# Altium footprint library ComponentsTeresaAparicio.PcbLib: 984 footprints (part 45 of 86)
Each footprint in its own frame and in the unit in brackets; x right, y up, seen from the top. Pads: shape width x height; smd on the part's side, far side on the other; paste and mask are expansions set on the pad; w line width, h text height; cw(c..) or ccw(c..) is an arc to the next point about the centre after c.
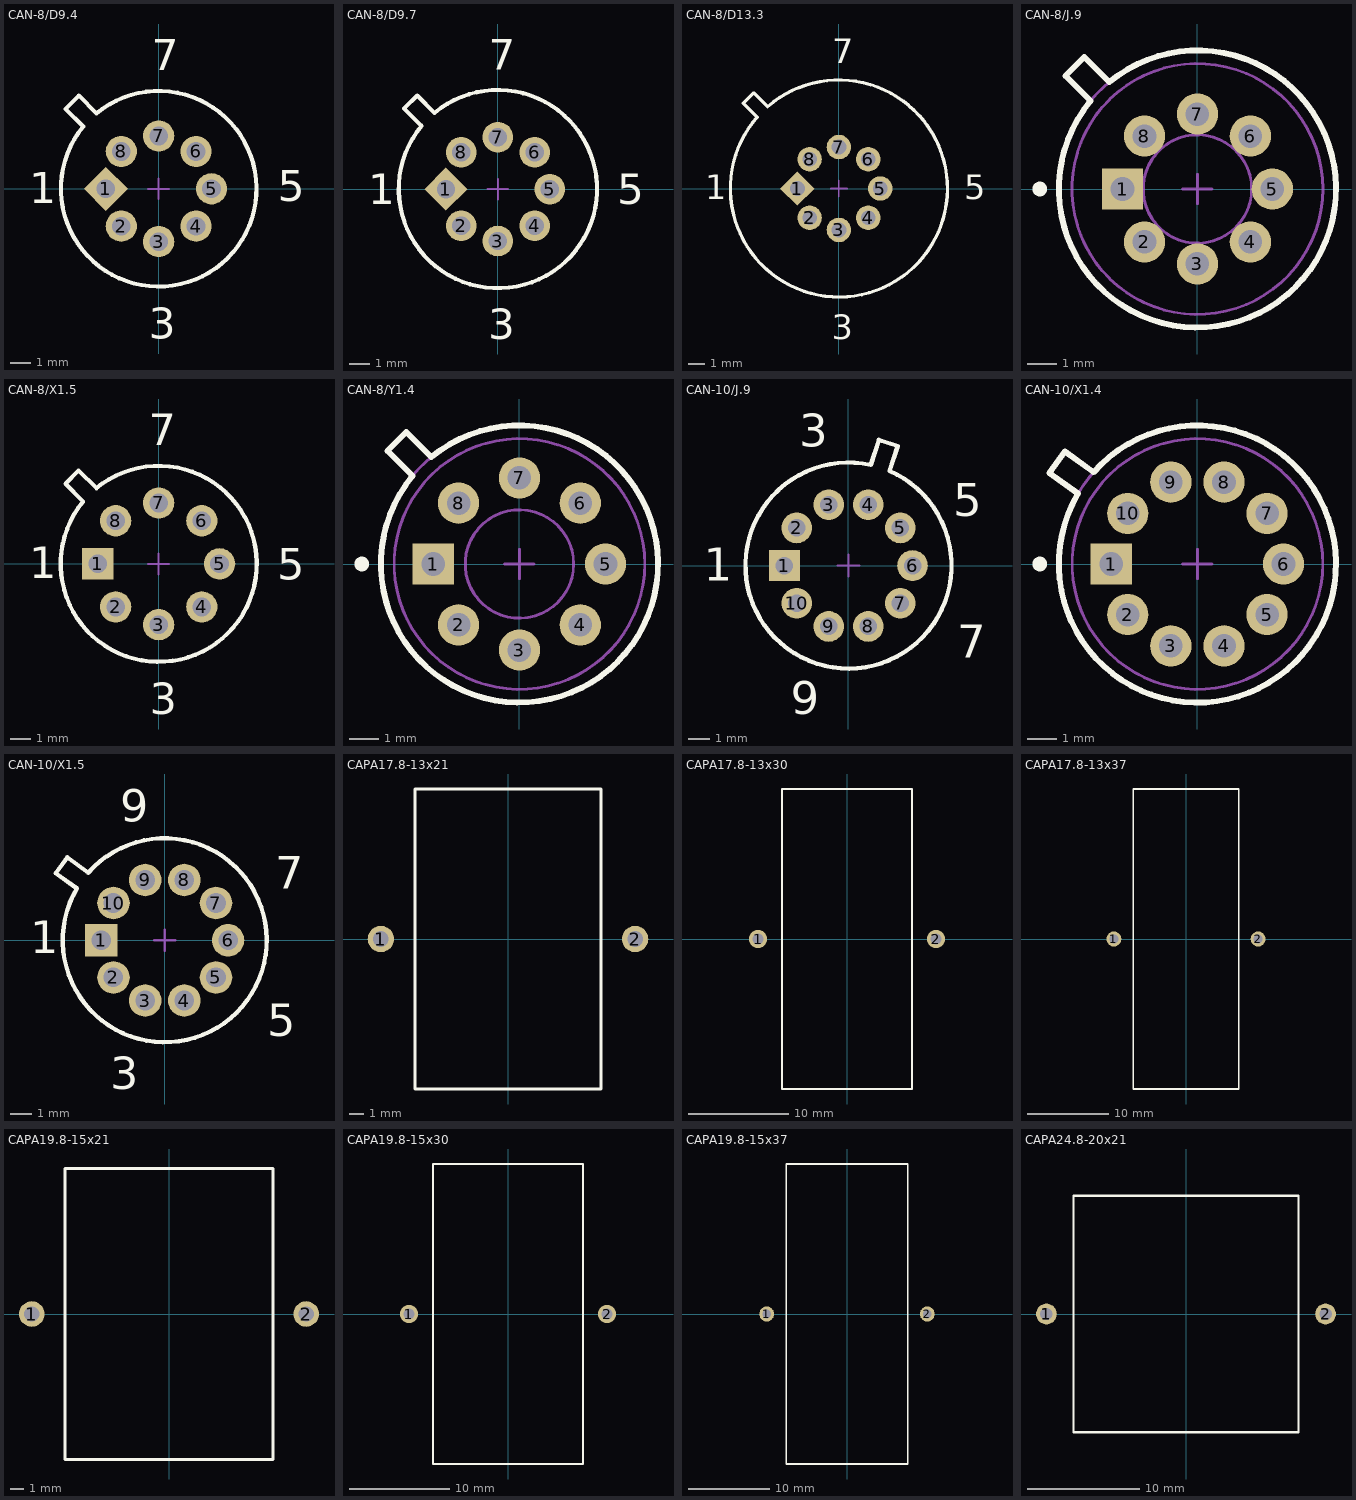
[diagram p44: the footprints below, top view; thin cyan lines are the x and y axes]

## CAN-8/D9.4 [mm] "Can; 8 Leads; Pin Circle Dia. 5.08 mm; Lead Dia. 0.53 mm (max)"
height 4.7
pads (8):
  rect 1.5x1.5 hole 0.9 rot 45: 1(-2.54,0)
  round 1.5 hole 0.9: 2(-1.796,-1.796) 3(0,-2.54) 4(1.796,-1.796) 5(2.54,0) 6(1.796,1.796) 7(0,2.54) 8(-1.796,1.796)
Top Overlay:
  lines w0.2: -4.475,3.838 -3.838,4.475 -2.99,3.626 cw(c0,0) -3.626,2.99 -4.475,3.838
  text "1" at -6.22,-0.696 h1.5
  text "3" at -0.469,-7.22 h1.5
  text "5" at 5.712,-0.589 h1.5
  text "7" at -0.332,5.7 h1.5
Mechanical 15:
  lines w0.1: -0.5,0 0.5,0 ; 0,-0.5 0,0.5

## CAN-8/D9.7 [mm] "Can; 8 Leads; Pin Circle Dia. 5.08 mm (TO-99); Lead Dia. 0.53 mm (max)"
height 5.72
pads (8):
  rect 1.5x1.5 hole 0.9 rot 45: 1(-2.54,0)
  round 1.5 hole 0.9: 2(-1.796,-1.796) 3(0,-2.54) 4(1.796,-1.796) 5(2.54,0) 6(1.796,1.796) 7(0,2.54) 8(-1.796,1.796)
Top Overlay:
  lines w0.2: -4.581,3.945 -3.733,3.096 ccw(c0,0) -3.096,3.733 -3.945,4.581 -4.581,3.945
  text "7" at -0.442,5.841 h1.5
  text "5" at 5.84,-0.737 h1.5
  text "3" at -0.479,-7.332 h1.5
  text "1" at -6.352,-0.737 h1.5
Mechanical 15:
  lines w0.1: -0.5,0 0.5,0 ; 0,-0.5 0,0.5

## CAN-8/D13.3 [mm] "Can; 8 Leads; Pin Circle Dia. 5.08 mm; Lead Dia. 0.53 mm (max)"
height 8.82
pads (8):
  rect 1.5x1.5 hole 0.9 rot 45: 1(-2.54,0)
  round 1.5 hole 0.9: 2(-1.796,-1.796) 3(0,-2.54) 4(1.796,-1.796) 5(2.54,0) 6(1.796,1.796) 7(0,2.54) 8(-1.796,1.796)
Top Overlay:
  lines w0.2: -5.858,5.222 -5.222,5.858 -4.373,5.01 cw(c0,0) -5.01,4.373 -5.858,5.222
  text "7" at -0.406,7.66 h1.5
  text "5" at 7.668,-0.667 h1.5
  text "3" at -0.431,-9.221 h1.5
  text "1" at -8.177,-0.667 h1.5
Mechanical 15:
  lines w0.1: -0.5,0 0.5,0 ; 0,-0.5 0,0.5

## CAN-8/J.9 [mm] "Can; 8 Leads; Pin Circle Dia. 5.08 mm; Lead Dia. 0.48 mm (max)"
height 5.56
pads (8):
  rect 1.4x1.4 hole 0.8: 1(-2.54,0)
  round 1.4 hole 0.8: 2(-1.796,-1.796) 3(0,-2.54) 4(1.796,-1.796) 5(2.54,0) 6(1.796,1.796) 7(0,2.54) 8(-1.796,1.796)
Top Overlay:
  circle w0.25: c-5.35,0 r0.125
  lines w0.2: -4.475,3.838 -3.626,2.99 ccw(c0,0) -2.99,3.626 -3.838,4.475 -4.475,3.838
Mechanical 13:
  circle w0.1: c0,0 r1.84
  circle w0.1: c0,0 r4.255
  circle w0.1: c0,0 r4.7
Mechanical 15:
  lines w0.1: -0.5,0 0.5,0 ; 0,-0.5 0,0.5
3D body: height 5.56, standoff 1.91, extent -4.264,-4.264 4.264,4.264
3D body: height 1.91, standoff 0.38, extent -4.71,-4.71 4.71,4.71
3D body: height 0.38, standoff 0, extent -1.848,-1.848 1.848,1.848

## CAN-8/X1.5 [mm] "Can; 8 Leads; Pin Circle Dia. 5.84 mm; Lead Dia. 0.53 mm (max)"
height 4.7
pads (8):
  rect 1.5x1.5 hole 0.9: 1(-2.92,0)
  round 1.5 hole 0.9: 2(-2.065,-2.065) 3(0,-2.92) 4(2.065,-2.065) 5(2.92,0) 6(2.065,2.065) 7(0,2.92) 8(-2.065,2.065)
Top Overlay:
  lines w0.2: -4.475,3.838 -3.626,2.99 ccw(c0,0) -2.99,3.626 -3.838,4.475 -4.475,3.838
  text "7" at -0.472,5.683 h1.5
  text "5" at 5.691,-0.769 h1.5
  text "3" at -0.436,-7.201 h1.5
  text "1" at -6.204,-0.697 h1.5
Mechanical 15:
  lines w0.1: -0.5,0 0.5,0 ; 0,-0.5 0,0.5

## CAN-8/Y1.4 [mm] "Can; 8 Leads; Pin Circle Dia. 5.84 mm; Lead Dia. 0.48 mm (max)"
height 5.08
pads (8):
  rect 1.4x1.4 hole 0.8: 1(-2.92,0)
  round 1.4 hole 0.8: 2(-2.065,-2.065) 3(0,-2.92) 4(2.065,-2.065) 5(2.92,0) 6(2.065,2.065) 7(0,2.92) 8(-2.065,2.065)
Top Overlay:
  circle w0.25: c-5.35,0 r0.125
  lines w0.2: -4.475,3.838 -3.626,2.99 ccw(c0,0) -2.99,3.626 -3.838,4.475 -4.475,3.838
Mechanical 13:
  circle w0.1: c0,0 r1.84
  circle w0.1: c0,0 r4.25
  circle w0.1: c0,0 r4.7
Mechanical 15:
  lines w0.1: -0.5,0 0.5,0 -0.5,0 ; 0,-0.5 0,0.5 0,-0.5
3D body: height 0.38, standoff 0, extent -1.848,-1.848 1.848,1.848
3D body: height 1.4, standoff 0.38, extent -4.71,-4.71 4.71,4.71
3D body: height 5.08, standoff 1.4, extent -4.259,-4.259 4.259,4.259

## CAN-10/J.9 [mm] "Can; 10 Leads; Pin Circle Dia. 5.84 mm; Lead Dia. 0.48 mm (max)"
height 4.7
pads (10):
  rect 1.4x1.4 hole 0.8: 1(-2.92,0)
  round 1.4 hole 0.8: 2(-2.362,1.716) 3(-0.902,2.777) 4(0.902,2.777) 5(2.362,1.716) 6(2.92,0) 7(2.362,-1.716) 8(0.902,-2.777) 9(-0.902,-2.777) 10(-2.362,-1.716)
Top Overlay:
  lines w0.2: 1.018,4.588 ccw(c0,0) 1.874,4.31 2.245,5.452 1.389,5.73 1.018,4.588
  text "1" at -6.596,-0.689 h1.5
  text "3" at -2.248,5.412 h1.5
  text "5" at 4.779,2.259 h1.5
  text "7" at 4.96,-4.21 h1.5
  text "9" at -2.636,-6.769 h1.5
Mechanical 15:
  lines w0.1: -0.5,0 0.5,0 ; 0,-0.5 0,0.5

## CAN-10/X1.4 [mm] "Can; 10 Leads; Pin Circle Dia. 5.84 mm; Lead Dia. 0.48 mm (max)"
height 4.7
pads (10):
  rect 1.4x1.4 hole 0.8: 1(-2.92,0)
  round 1.4 hole 0.8: 2(-2.362,-1.716) 3(-0.902,-2.777) 4(0.902,-2.777) 5(2.362,-1.716) 6(2.92,0) 7(2.362,1.716) 8(0.902,2.777) 9(-0.902,2.777) 10(-2.362,1.716)
Top Overlay:
  circle w0.25: c-5.35,0 r0.125
  lines w0.2: -4.049,2.386 -5.02,3.091 -4.491,3.819 -3.52,3.114 cw(c0,0) -4.049,2.386
Mechanical 13:
  circle w0.1: c0,0 r4.25
  circle w0.1: c0,0 r4.7
Mechanical 15:
  lines w0.1: -0.5,0 0.5,0 ; 0,-0.5 0,0.5
3D body: height 0.89, standoff 0, extent -4.71,-4.71 4.71,4.71
3D body: height 4.7, standoff 0.89, extent -4.259,-4.259 4.259,4.259

## CAN-10/X1.5 [mm] "Can; 10 Leads; Pin Circle Dia. 5.84 mm; Lead Dia. 0.53 mm (max)"
height 4.7
pads (10):
  rect 1.5x1.5 hole 0.9: 1(-2.92,0)
  round 1.5 hole 0.9: 2(-2.362,-1.716) 3(-0.902,-2.777) 4(0.902,-2.777) 5(2.362,-1.716) 6(2.92,0) 7(2.362,1.716) 8(0.902,2.777) 9(-0.902,2.777) 10(-2.362,1.716)
Top Overlay:
  lines w0.2: -4.049,2.386 -5.02,3.091 -4.491,3.819 -3.52,3.114 cw(c0,0) -4.049,2.386
  text "9" at -2.056,5.471 h1.5
  text "7" at 5.1,2.376 h1.5
  text "5" at 4.736,-4.434 h1.5
  text "3" at -2.511,-6.856 h1.5
  text "1" at -6.207,-0.592 h1.5
Mechanical 15:
  lines w0.1: -0.5,0 0.5,0 ; 0,-0.5 0,0.5

## CAPA17.8-13x21 [mm] "Capacitor, Ceramic, Thru-Hole, Axial Leads; Body 13 x 21 mm (LxDia. max) Pin Spacing 17.8 mm (typ)"
height 21
pads (2):
  round 1.85 hole 1.1: 1(-8.9,0) 2(8.9,0)
Top Overlay:
  lines w0.2: -6.5,-10.5 6.5,-10.5 6.5,10.5 -6.5,10.5 -6.5,-10.5

## CAPA17.8-13x30 [mm] "Capacitor, Ceramic, Thru-Hole, Axial Leads; Body 13 x 30 mm (LxDia. max) Pin Spacing 17.8 mm (typ)"
height 30
pads (2):
  round 1.85 hole 1.1: 1(-8.9,0) 2(8.9,0)
Top Overlay:
  lines w0.2: -6.5,-15 6.5,-15 6.5,15 -6.5,15 -6.5,-15

## CAPA17.8-13x37 [mm] "Capacitor, Ceramic, Thru-Hole, Axial Leads; Body 13 x 37 mm (LxDia. max) Pin Spacing 17.8 mm (typ)"
height 37
pads (2):
  round 1.85 hole 1.1: 1(-8.9,0) 2(8.9,0)
Top Overlay:
  lines w0.2: -6.5,-18.5 -6.5,18.5 6.5,18.5 6.5,-18.5 -6.5,-18.5

## CAPA19.8-15x21 [mm] "Capacitor, Ceramic, Thru-Hole, Axial Leads; Body 15 x 21 mm (LxDia. max) Pin Spacing 19.8 mm (typ)"
height 21
pads (2):
  round 1.85 hole 1.1: 1(-9.9,0) 2(9.9,0)
Top Overlay:
  lines w0.2: -7.5,-10.5 -7.5,10.5 7.5,10.5 7.5,-10.5 -7.5,-10.5

## CAPA19.8-15x30 [mm] "Capacitor, Ceramic, Thru-Hole, Axial Leads; Body 15 x 30 mm (LxDia. max) Pin Spacing 19.8 mm (typ)"
height 30
pads (2):
  round 1.85 hole 1.1: 1(-9.9,0) 2(9.9,0)
Top Overlay:
  lines w0.2: -7.5,-15 7.5,-15 7.5,15 -7.5,15 -7.5,-15

## CAPA19.8-15x37 [mm] "Capacitor, Ceramic, Thru-Hole, Axial Leads; Body 15 x 37 mm (LxDia. max) Pin Spacing 19.8 mm (typ)"
height 37
pads (2):
  round 1.85 hole 1.1: 1(-9.9,0) 2(9.9,0)
Top Overlay:
  lines w0.2: -7.5,-18.5 -7.5,18.5 7.5,18.5 7.5,-18.5 -7.5,-18.5

## CAPA24.8-20x21 [mm] "Capacitor, Ceramic, Thru-Hole, Axial Leads; Body 20 x 21 mm (LxDia. max) Pin Spacing 24.8 mm (typ)"
height 21
pads (2):
  round 1.85 hole 1.1: 1(-12.4,0) 2(12.4,0)
Top Overlay:
  lines w0.2: -10,-10.5 10,-10.5 10,10.5 -10,10.5 -10,-10.5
